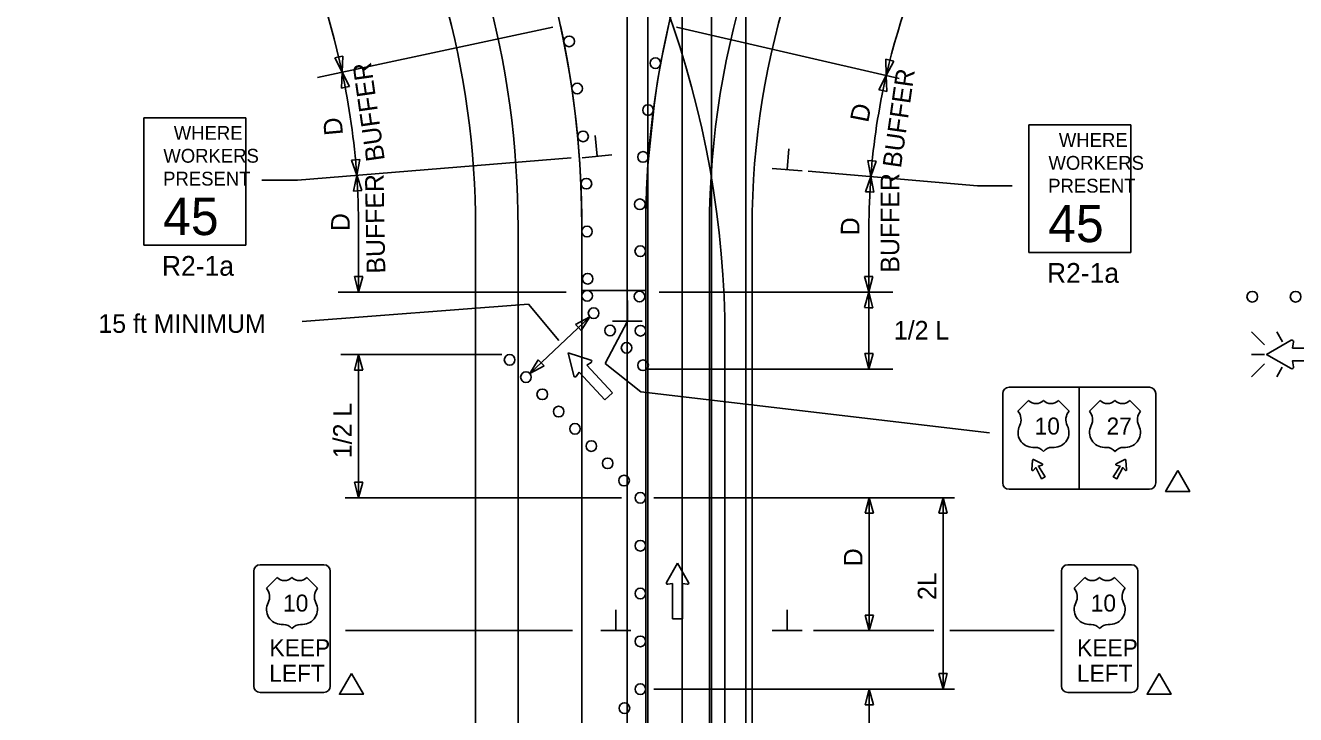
# Model space of a CAD drawing. Extents: x 16452 to 19504, y 5713 to 7079.
# Drawn here: x 16746.6 to 17224.4, y 6242.5 to 6501.7 of the extents above; entities that cross this region are included whole.
import ezdxf

# ---------------------------------------------------------------- set-up
doc = ezdxf.new("R2010")
doc.units = 0
for name, color, linetype in [('ALI_LEGAL_EX', 7, 'Continuous'), ('MT_SCRATCH_LEVEL_E', 7, 'Continuous'), ('PAVT_EDGE_EX', 7, 'Continuous'), ('TRAFFIC_SIGNS_PR', 7, 'Continuous'), ('TYPICAL_EX', 7, 'Continuous'), ('TYPICAL_TEXT_DIMEN_PR', 7, 'Continuous')]:
    doc.layers.add(name, color=color, linetype=linetype)

msp = doc.modelspace()

# ---------------------------------------------------------------- linework, layer by layer
at = {"layer": 'ALI_LEGAL_EX'}
for p, q in [((16980.68, 7015.93), (16980.68, 6197.8)), ((17004.68, 7015.93), (17004.68, 6197.8)), ((16980.68, 6877.04), (16980.68, 6013.12)), ((17004.68, 6877.04), (17004.68, 6013.12)), ((16973.01, 6180.85), (16973.01, 6681.19)), ((16993.65, 6024.8), (16993.65, 6525.15)), ((17017.65, 6024.8), (17017.65, 6525.15)), ((16955.93, 6148.9), (16955.93, 6425.58)), ((16979.93, 6148.9), (16979.93, 6425.58)), ((17009.75, 5773.57), (17009.75, 6383.76))]:
    msp.add_line(p, q, dxfattribs=at)
for points in [[(16980.7, 6449.11), (16983.32, 6473.98)], [(16955.93, 6270.95), (16955.93, 6295.95)], [(16979.93, 6270.95), (16979.93, 6295.95)]]:
    msp.add_lwpolyline(points, dxfattribs=at)
for centre, radius, start, end in [((16591.93, 6425.58), 364, 0, 40.1909), ((17319.93, 6425.58), 340, 137.516, 180), ((16645.75, 6383.76), 364, 0, 40.1909)]:
    msp.add_arc(centre, radius, start, end, dxfattribs=at)
at = {"layer": 'MT_SCRATCH_LEVEL_E'}
for p, q in [((16991.9, 6299.43), (16987.79, 6292.19)), ((16996.05, 6292.19), (16991.9, 6299.43)), ((16988.27, 6291.5), (16990.05, 6291.82)), ((16990.05, 6291.82), (16990.05, 6278.56)), ((16993.79, 6278.56), (16993.79, 6291.82)), ((16993.79, 6291.82), (16995.57, 6291.5)), ((16990.05, 6278.56), (16993.79, 6278.56))]:
    msp.add_line(p, q, dxfattribs=at)
for centre, start, end in [((16988.2, 6291.96), 150.4248, 279.9638), ((16995.64, 6291.96), 260.0362, 29.7731)]:
    msp.add_arc(centre, 0.463, start, end, dxfattribs=at)
at = {"layer": 'PAVT_EDGE_EX'}
for p, q in [((16915.93, 6425.58), (16915.93, 6070.95)), ((16931.93, 6425.58), (16931.93, 6070.95)), ((16955.93, 6425.58), (16955.93, 6070.95)), ((16955.93, 6425.58), (16955.93, 6402.03)), ((16979.93, 6425.58), (16979.93, 6070.95)), ((16979.93, 6402.03), (16979.93, 6425.58)), ((17003.93, 6425.58), (17003.93, 6070.95)), ((17019.93, 6425.58), (17019.93, 6070.95)), ((16955.93, 6402.03), (16979.93, 6402.03))]:
    msp.add_line(p, q, dxfattribs=at)
for centre, radius, start, end in [((16591.93, 6425.58), 340, 0, 61.4862), ((17319.93, 6425.58), 316, 107.923, 180), ((16591.93, 6425.58), 324, 0, 61.4862), ((17319.93, 6425.58), 300, 107.923, 180), ((16591.93, 6425.58), 364, 0, 12.0742), ((17319.93, 6425.58), 340, 167.0592, 180), ((17319.93, 6425.58), 300, 180, 180.00000277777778)]:
    msp.add_arc(centre, radius, start, end, dxfattribs=at)
at = {"layer": 'TRAFFIC_SIGNS_PR'}
for p, q in [((16791.11, 6467), (16829.51, 6467)), ((16791.11, 6419), (16791.11, 6467)), ((16829.51, 6419), (16829.51, 6467)), ((17124.04, 6464.34), (17162.44, 6464.34)), ((17124.04, 6416.34), (17124.04, 6464.34)), ((17162.44, 6416.34), (17162.44, 6464.34)), ((16791.11, 6419), (16829.51, 6419)), ((17124.04, 6416.34), (17162.44, 6416.34)), ((17207.78, 6386.48), (17212.71, 6381.55)), ((17219.54, 6382.66), (17217.33, 6386.48)), ((17212.71, 6377.99), (17207.78, 6377.99)), ((17207.78, 6369.51), (17212.71, 6374.44)), ((17217.29, 6369.5), (17219.4, 6373.17)), ((17116.62, 6365.62), (17169.42, 6365.62)), ((17143.02, 6365.62), (17143.02, 6327.22)), ((17114.22, 6363.22), (17114.22, 6329.62)), ((17171.82, 6363.22), (17171.82, 6329.62)), ((17125.2, 6334.57), (17125.48, 6338.19)), ((17125.86, 6338.4), (17129.13, 6336.84)), ((17160.19, 6338.4), (17156.91, 6336.84)), ((17160.84, 6334.57), (17160.56, 6338.19)), ((17116.62, 6327.22), (17169.42, 6327.22)), ((16858.87, 6298.83), (16834.87, 6298.83)), ((17162.69, 6298.83), (17138.69, 6298.83)), ((16832.47, 6296.43), (16832.47, 6253.23)), ((16861.27, 6253.23), (16861.27, 6296.43)), ((17136.3, 6296.43), (17136.3, 6253.23)), ((17165.1, 6253.23), (17165.1, 6296.43)), ((16834.87, 6250.83), (16858.87, 6250.83)), ((17138.69, 6250.83), (17162.69, 6250.83))]:
    msp.add_line(p, q, dxfattribs=at)
for points in [[(17222.79, 6383.27), (17213.5, 6377.99), (17222.79, 6372.67)], [(17223.66, 6373.3), (17223.26, 6375.57), (17240.28, 6375.57), (17240.28, 6380.37), (17223.26, 6380.37), (17223.67, 6382.65)], [(17129.09, 6336.35), (17127.69, 6335.97), (17130.2, 6331.98), (17128.87, 6331.22), (17126.68, 6335.39), (17125.64, 6334.36)], [(17156.95, 6336.35), (17158.36, 6335.97), (17155.84, 6331.98), (17157.17, 6331.22), (17159.36, 6335.39), (17160.4, 6334.36)]]:
    msp.add_lwpolyline(points, dxfattribs=at)
for centre in [(16951.15, 6495.71), (16983.59, 6487.52), (16954.16, 6477.97), (16954.16, 6477.97), (16980.81, 6469.87), (16956.38, 6459.96), (16978.92, 6452.23), (16957.62, 6442.19), (16977.75, 6434.44), (16957.86, 6424.18), (16977.9, 6416.79), (16958.11, 6406.42), (16957.94, 6400.01), (16977.61, 6399.73), (17208.12, 6399.68), (17224.42, 6399.68), (16960.35, 6393.48), (16966.54, 6386.95), (16977.98, 6386.88), (16972.74, 6380.42), (16928.74, 6375.92), (16978.94, 6373.88), (16934.89, 6369.43), (16941.04, 6362.95), (16947.19, 6356.46), (16953.34, 6349.97), (16959.48, 6343.49), (16965.63, 6337), (16971.78, 6330.51), (16977.93, 6324.02), (16977.93, 6324.02), (16977.93, 6306.02), (16977.93, 6288.02), (16977.93, 6270.02), (16977.93, 6252.07), (16971.93, 6244.93)]:
    msp.add_circle(centre, 2, dxfattribs=at)
for centre, radius, start, end in [((17223.08, 6382.75), 0.598, 350.7308, 118.8916), ((17223.07, 6373.2), 0.597, 241.4833, 9.9593), ((17116.62, 6363.22), 2.4, 90, 180), ((17116.62, 6363.22), 2.4, 90, 180), ((17169.42, 6363.22), 2.4, 0, 90), ((17125.74, 6338.17), 0.26, 64.4823, 175.5177), ((17129.02, 6336.6), 0.26, 285.9885, 64.4823), ((17157.02, 6336.6), 0.26, 115.5177, 254.0115), ((17160.3, 6338.17), 0.26, 4.4823, 115.5177), ((17125.46, 6334.55), 0.26, 175.5177, 314.0115), ((17160.58, 6334.55), 0.26, 225.9885, 4.4823), ((17116.62, 6329.62), 2.4, 180, 270), ((17169.42, 6329.62), 2.4, 270, 0), ((16834.87, 6296.43), 2.4, 90, 180), ((16858.87, 6296.43), 2.4, 0, 90), ((17138.69, 6296.43), 2.4, 90, 180), ((17162.69, 6296.43), 2.4, 0, 90), ((16834.87, 6253.23), 2.4, 180, 270), ((16858.87, 6253.23), 2.4, 270, 0), ((17138.69, 6253.23), 2.4, 180, 270), ((17162.69, 6253.23), 2.4, 270, 0)]:
    msp.add_arc(centre, radius, start, end, dxfattribs=at)
at = {"layer": 'TYPICAL_EX'}
for p, q in [((17119.97, 6356.62), (17123.97, 6360.62)), ((17139.17, 6356.62), (17135.17, 6360.62)), ((17146.87, 6356.62), (17150.87, 6360.62)), ((17166.07, 6356.62), (17162.07, 6360.62)), ((17125.57, 6343.01), (17126.37, 6343.01)), ((17133.58, 6343.01), (17132.78, 6343.01)), ((17152.47, 6343.01), (17153.27, 6343.01)), ((17160.48, 6343.01), (17159.68, 6343.01)), ((16837.27, 6290.03), (16841.27, 6294.03)), ((16856.47, 6290.03), (16852.47, 6294.03)), ((17141.1, 6290.03), (17145.1, 6294.03)), ((17160.3, 6290.03), (17156.3, 6294.03)), ((16842.87, 6276.42), (16843.67, 6276.42)), ((16850.88, 6276.42), (16850.08, 6276.42)), ((17146.69, 6276.42), (17147.49, 6276.42)), ((17154.7, 6276.42), (17153.9, 6276.42))]:
    msp.add_line(p, q, dxfattribs=at)
for centre, radius, start, end in [((17126.77, 6363.53), 4.04, 226.1404, 313.8596), ((17132.37, 6363.53), 4.04, 226.1404, 313.8596), ((17153.67, 6363.53), 4.04, 226.1404, 313.8596), ((17159.27, 6363.53), 4.04, 226.1404, 313.8596), ((17116.18, 6353.42), 4.96, 333.0977, 40.1936), ((17142.96, 6353.42), 4.96, 139.8064, 206.9023), ((17143.08, 6353.42), 4.96, 333.0977, 40.1936), ((17169.86, 6353.42), 4.96, 139.8064, 206.9023), ((17125.58, 6348.6), 5.59, 152.6698, 269.9013), ((17133.57, 6348.6), 5.59, 270.0987, 27.3302), ((17152.48, 6348.6), 5.59, 152.6698, 269.9013), ((17160.47, 6348.6), 5.59, 270.0987, 27.3302), ((17126.38, 6339), 4.01, 37.1038, 90.1385), ((17132.77, 6339), 4.01, 89.8615, 142.8962), ((17153.28, 6339), 4.01, 37.1038, 90.1385), ((17159.67, 6339), 4.01, 89.8615, 142.8962), ((16844.07, 6296.94), 4.04, 226.1404, 313.8596), ((16849.67, 6296.94), 4.04, 226.1404, 313.8596), ((17147.89, 6296.94), 4.04, 226.1404, 313.8596), ((17153.49, 6296.94), 4.04, 226.1404, 313.8596), ((16833.48, 6286.82), 4.96, 333.0977, 40.1936), ((16860.26, 6286.82), 4.96, 139.8064, 206.9023), ((17137.3, 6286.82), 4.96, 333.0977, 40.1936), ((17164.08, 6286.82), 4.96, 139.8064, 206.9023), ((16842.88, 6282.01), 5.59, 152.6698, 269.9013), ((16850.87, 6282.01), 5.59, 270.0987, 27.3302), ((17146.7, 6282.01), 5.59, 152.6698, 269.9013), ((17154.69, 6282.01), 5.59, 270.0987, 27.3302), ((16843.68, 6272.41), 4.01, 37.1038, 90.1385), ((16850.07, 6272.41), 4.01, 89.8615, 142.8962), ((17147.5, 6272.41), 4.01, 37.1038, 90.1385), ((17153.89, 6272.41), 4.01, 89.8615, 142.8962)]:
    msp.add_arc(centre, radius, start, end, dxfattribs=at)
at = {"layer": 'TYPICAL_TEXT_DIMEN_PR'}
for p, q in [((16856.49, 6482.17), (16944.94, 6501.09)), ((17075.31, 6481.79), (16991.54, 6501.03)), ((16862.97, 6489.55), (16864.51, 6489.88)), ((16865.74, 6484.15), (16862.97, 6489.55)), ((16864.51, 6489.88), (16866.05, 6490.21)), ((16866.05, 6490.21), (16865.74, 6484.15)), ((17070.43, 6482.91), (17070.22, 6488.97)), ((17070.22, 6488.97), (17071.75, 6488.62)), ((16865.48, 6478.08), (16865.74, 6484.15)), ((16865.74, 6484.15), (16868.55, 6478.77)), ((17073.28, 6488.27), (17070.43, 6482.91)), ((17071.75, 6488.62), (17073.28, 6488.27)), ((17067.59, 6477.54), (17070.43, 6482.91)), ((17070.43, 6482.91), (17070.65, 6476.84)), ((16867.02, 6478.43), (16865.48, 6478.08)), ((16868.55, 6478.77), (16867.02, 6478.43)), ((17069.12, 6477.19), (17067.59, 6477.54)), ((17070.65, 6476.84), (17069.12, 6477.19)), ((16961.63, 6452.52), (16960.88, 6460.27)), ((17033.16, 6447.48), (17033.82, 6455.24)), ((16951.9, 6451.87), (16848.91, 6443.55)), ((16869.21, 6451.08), (16870.77, 6451.2)), ((16871.23, 6445.36), (16869.21, 6451.08)), ((16870.77, 6451.2), (16872.34, 6451.32)), ((16872.34, 6451.32), (16871.23, 6445.36)), ((16967.23, 6453.06), (16956.04, 6451.97)), ((17065.1, 6450.75), (17063.53, 6450.88)), ((17063.53, 6450.88), (17064.64, 6444.91)), ((17064.64, 6444.91), (17066.67, 6450.63)), ((17066.67, 6450.63), (17065.1, 6450.75)), ((17038.76, 6447), (17027.55, 6447.95)), ((17041.06, 6446.95), (17104.76, 6441.43)), ((16848.91, 6443.55), (16835.5, 6443.55)), ((16870.06, 6439.4), (16871.23, 6445.36)), ((16871.23, 6445.36), (16873.19, 6439.61)), ((17064.64, 6444.91), (17062.64, 6439.18)), ((17065.77, 6438.95), (17064.64, 6444.91)), ((17117.83, 6441.43), (17104.76, 6441.43)), ((16871.62, 6439.51), (16870.06, 6439.4)), ((16873.19, 6439.61), (16871.62, 6439.51)), ((17062.64, 6439.18), (17064.2, 6439.06)), ((17064.2, 6439.06), (17065.77, 6438.95)), ((16871.93, 6425.58), (16871.93, 6401.4)), ((17063.91, 6425.58), (17063.91, 6401.4)), ((16871.93, 6401.4), (16870.36, 6407.26)), ((16870.36, 6407.26), (16871.93, 6407.26)), ((16871.93, 6407.26), (16873.5, 6407.26)), ((16873.5, 6407.26), (16871.93, 6401.4)), ((17063.86, 6407.32), (17062.29, 6407.31)), ((17062.29, 6407.31), (17063.91, 6401.46)), ((17065.43, 6407.33), (17063.86, 6407.32)), ((17063.91, 6401.46), (17065.43, 6407.33)), ((16864.23, 6401.4), (16950.08, 6401.4)), ((16973.04, 6390.52), (16973.04, 6398.3)), ((16984.99, 6401.4), (17072.88, 6401.4)), ((17062.29, 6395.55), (17063.91, 6401.4)), ((17063.91, 6401.4), (17065.43, 6395.52)), ((17063.91, 6401.4), (17063.91, 6372.48)), ((16935.91, 6396.88), (16850.71, 6390.33)), ((16947.27, 6383.19), (16935.91, 6396.88)), ((17063.86, 6395.54), (17062.29, 6395.55)), ((17065.43, 6395.52), (17063.86, 6395.54)), ((16958.9, 6392.11), (16936.35, 6370.81)), ((16953.56, 6389.23), (16958.9, 6392.11)), ((16954.64, 6388.08), (16953.56, 6389.23)), ((16958.9, 6392.11), (16955.72, 6386.94)), ((16973.04, 6390.52), (16964.73, 6374.54)), ((16978.66, 6390.52), (16967.41, 6390.52)), ((16955.72, 6386.94), (16954.64, 6388.08)), ((16865.26, 6377.92), (16925.83, 6377.92)), ((16870.36, 6372.06), (16871.93, 6377.92)), ((16871.93, 6377.92), (16871.93, 6324.07)), ((16871.93, 6377.92), (16873.5, 6372.06)), ((16936.35, 6370.81), (16939.53, 6375.97)), ((16939.53, 6375.97), (16940.61, 6374.83)), ((16940.61, 6374.83), (16941.69, 6373.69)), ((16959.32, 6375.86), (16950.83, 6378.53)), ((16950.83, 6378.53), (16952.85, 6369.88)), ((16957.82, 6373.94), (16959.44, 6374.98)), ((16978.14, 6363.84), (16964.73, 6374.54)), ((17063.91, 6372.48), (17062.39, 6378.36)), ((17062.39, 6378.36), (17063.96, 6378.35)), ((17065.53, 6378.33), (17063.91, 6372.48)), ((17063.96, 6378.35), (17065.53, 6378.33)), ((16871.93, 6372.06), (16870.36, 6372.06)), ((16873.5, 6372.06), (16871.93, 6372.06)), ((16941.69, 6373.69), (16936.35, 6370.81)), ((16953.73, 6369.69), (16954.89, 6371.23)), ((16954.89, 6371.23), (16964.5, 6360.85)), ((16967.43, 6363.56), (16957.82, 6373.94)), ((16979.93, 6372.48), (17072.88, 6372.48)), ((16964.5, 6360.85), (16967.43, 6363.56)), ((16978.14, 6363.84), (17109.28, 6348.49)), ((16871.93, 6324.07), (16870.36, 6329.94)), ((16870.36, 6329.94), (16871.93, 6329.94)), ((16871.93, 6329.94), (16873.5, 6329.94)), ((16873.5, 6329.94), (16871.93, 6324.07)), ((16970.82, 6324.07), (16866.93, 6324.07)), ((17096.07, 6324.07), (16982.98, 6324.07)), ((17062.46, 6318.21), (17064.03, 6324.07)), ((17064.03, 6324.07), (17065.6, 6318.21)), ((17064.03, 6324.07), (17064.03, 6274.07)), ((17090.26, 6318.21), (17091.83, 6324.07)), ((17091.83, 6324.07), (17091.83, 6252.07)), ((17091.83, 6324.07), (17093.4, 6318.21)), ((17064.03, 6318.21), (17062.46, 6318.21)), ((17065.6, 6318.21), (17064.03, 6318.21)), ((17091.83, 6318.21), (17090.26, 6318.21)), ((17093.4, 6318.21), (17091.83, 6318.21)), ((16968.68, 6274.07), (16968.68, 6281.86)), ((17033.15, 6274.07), (17033.15, 6281.86)), ((17064.03, 6274.07), (17062.46, 6279.94)), ((17062.46, 6279.94), (17064.03, 6279.94)), ((17064.03, 6279.94), (17065.6, 6279.94)), ((17065.6, 6279.94), (17064.03, 6274.07)), ((16867.03, 6274.07), (16952.43, 6274.07)), ((16974.31, 6274.07), (16963.06, 6274.07)), ((17038.78, 6274.07), (17027.53, 6274.07)), ((17088.3, 6274.07), (17043.03, 6274.07)), ((17133.57, 6274.07), (17094.37, 6274.07)), ((17091.83, 6252.07), (17090.26, 6257.94)), ((17090.26, 6257.94), (17091.83, 6257.94)), ((17091.83, 6257.94), (17093.4, 6257.94)), ((17093.4, 6257.94), (17091.83, 6252.07)), ((16982.98, 6252.07), (17096.07, 6252.07)), ((17062.46, 6246.21), (17064.03, 6252.07)), ((17064.03, 6223.51), (17064.03, 6252.07)), ((17064.03, 6252.07), (17065.6, 6246.21)), ((17064.03, 6246.21), (17062.46, 6246.21)), ((17065.6, 6246.21), (17064.03, 6246.21))]:
    msp.add_line(p, q, dxfattribs=at)
for points in [[(17180.05, 6334.29), (17175.53, 6326.45), (17184.58, 6326.45)], [(16869.24, 6258), (16864.71, 6250.17), (16873.76, 6250.17)], [(17173.06, 6258), (17168.54, 6250.17), (17177.59, 6250.17)]]:
    msp.add_lwpolyline(points, close=True, dxfattribs=at)
for centre, radius, start, end in [((16591.93, 6425.58), 280, 12.0744, 40.102), ((17319.93, 6425.58), 256, 137.0843, 167.0592), ((16591.93, 6425.58), 280, 4.0506, 12.0743), ((17319.93, 6425.58), 256.02, 167.0592, 175.6695), ((16591.93, 6425.58), 280, 0, 4.0506), ((17319.93, 6425.58), 256.02, 175.6695, 180), ((16959.16, 6375.39), 0.494, 302.8238, 72.5607), ((16953.34, 6370), 0.494, 193.2124, 322.7514)]:
    msp.add_arc(centre, radius, start, end, dxfattribs=at)

# ---------------------------------------------------------------- texts
at = {"layer": 'TRAFFIC_SIGNS_PR'}
for s, height, p in [('WHERE', 5.2, (16802.42, 6458.68)), ('WHERE', 5.2, (17135.35, 6456.02)), ('WORKERS', 5.2, (16798.49, 6450.08)), ('WORKERS', 5.2, (17131.43, 6447.42)), ('PRESENT', 5.2, (16798.42, 6441.48)), ('PRESENT', 5.2, (17131.36, 6438.82)), ('45', 14.031, (16798.41, 6422.85)), ('45', 14.031, (17131.35, 6420.19)), ('R2-1a', 7.44, (16797.96, 6407.56)), ('R2-1a', 7.44, (17130.9, 6404.9)), ('10', 6.4, (17126.23, 6347.82)), ('27', 6.4, (17153.3, 6347.82)), ('10', 6.4, (16843.53, 6281.23)), ('10', 6.4, (17147.35, 6281.23)), ('KEEP', 6.4, (16838.41, 6264.43)), ('KEEP', 6.4, (17142.23, 6264.43)), ('LEFT', 6.4, (16838.32, 6254.83)), ('LEFT', 6.4, (17142.14, 6254.83))]:
    msp.add_text(s, height=height, dxfattribs=at).set_placement(p)
at = {"layer": 'TYPICAL_TEXT_DIMEN_PR'}
for s, rotation, p in [('BUFFER', 98.1044, (16881.83, 6451.09)), ('BUFFER', 81.8794, (17075.93, 6447.82)), ('D', 78.9226, (17063.61, 6464.92)), ('D', 95.1476, (16866.09, 6460.64)), ('BUFFER', 89.9795, (17075.31, 6408.71)), ('BUFFER', 91.0079, (16881.99, 6408.42)), ('D', 90.2167, (16868.61, 6424.35)), ('D', 89.8868, (17060.33, 6422.77)), ('1/2 L', 90, (16869.37, 6338.94)), ('D', 90, (17061.47, 6298.29)), ('2L', 90, (17089.28, 6285.58))]:
    msp.add_text(s, height=7, rotation=rotation, dxfattribs=at).set_placement(p)
for s, p in [('15 ft MINIMUM', (16774.06, 6386.08)), ('1/2 L', (17073.3, 6383.57))]:
    msp.add_text(s, height=7, dxfattribs=at).set_placement(p)

doc.saveas('drawing.dxf')
